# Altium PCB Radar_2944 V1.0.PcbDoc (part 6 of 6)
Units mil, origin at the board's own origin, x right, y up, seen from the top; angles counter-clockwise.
Board outline 3544.83 x 2556.65 mil, 8 copper layers (Top Layer, GND1, SIG1, PWR1, PWR2, SIG2, GND2, Bottom Layer), stack 55.2 mil thick; 301 components, 253 nets, 1055 pads, 1340 vias.
Unrouted connection lines stored in the file: 12.
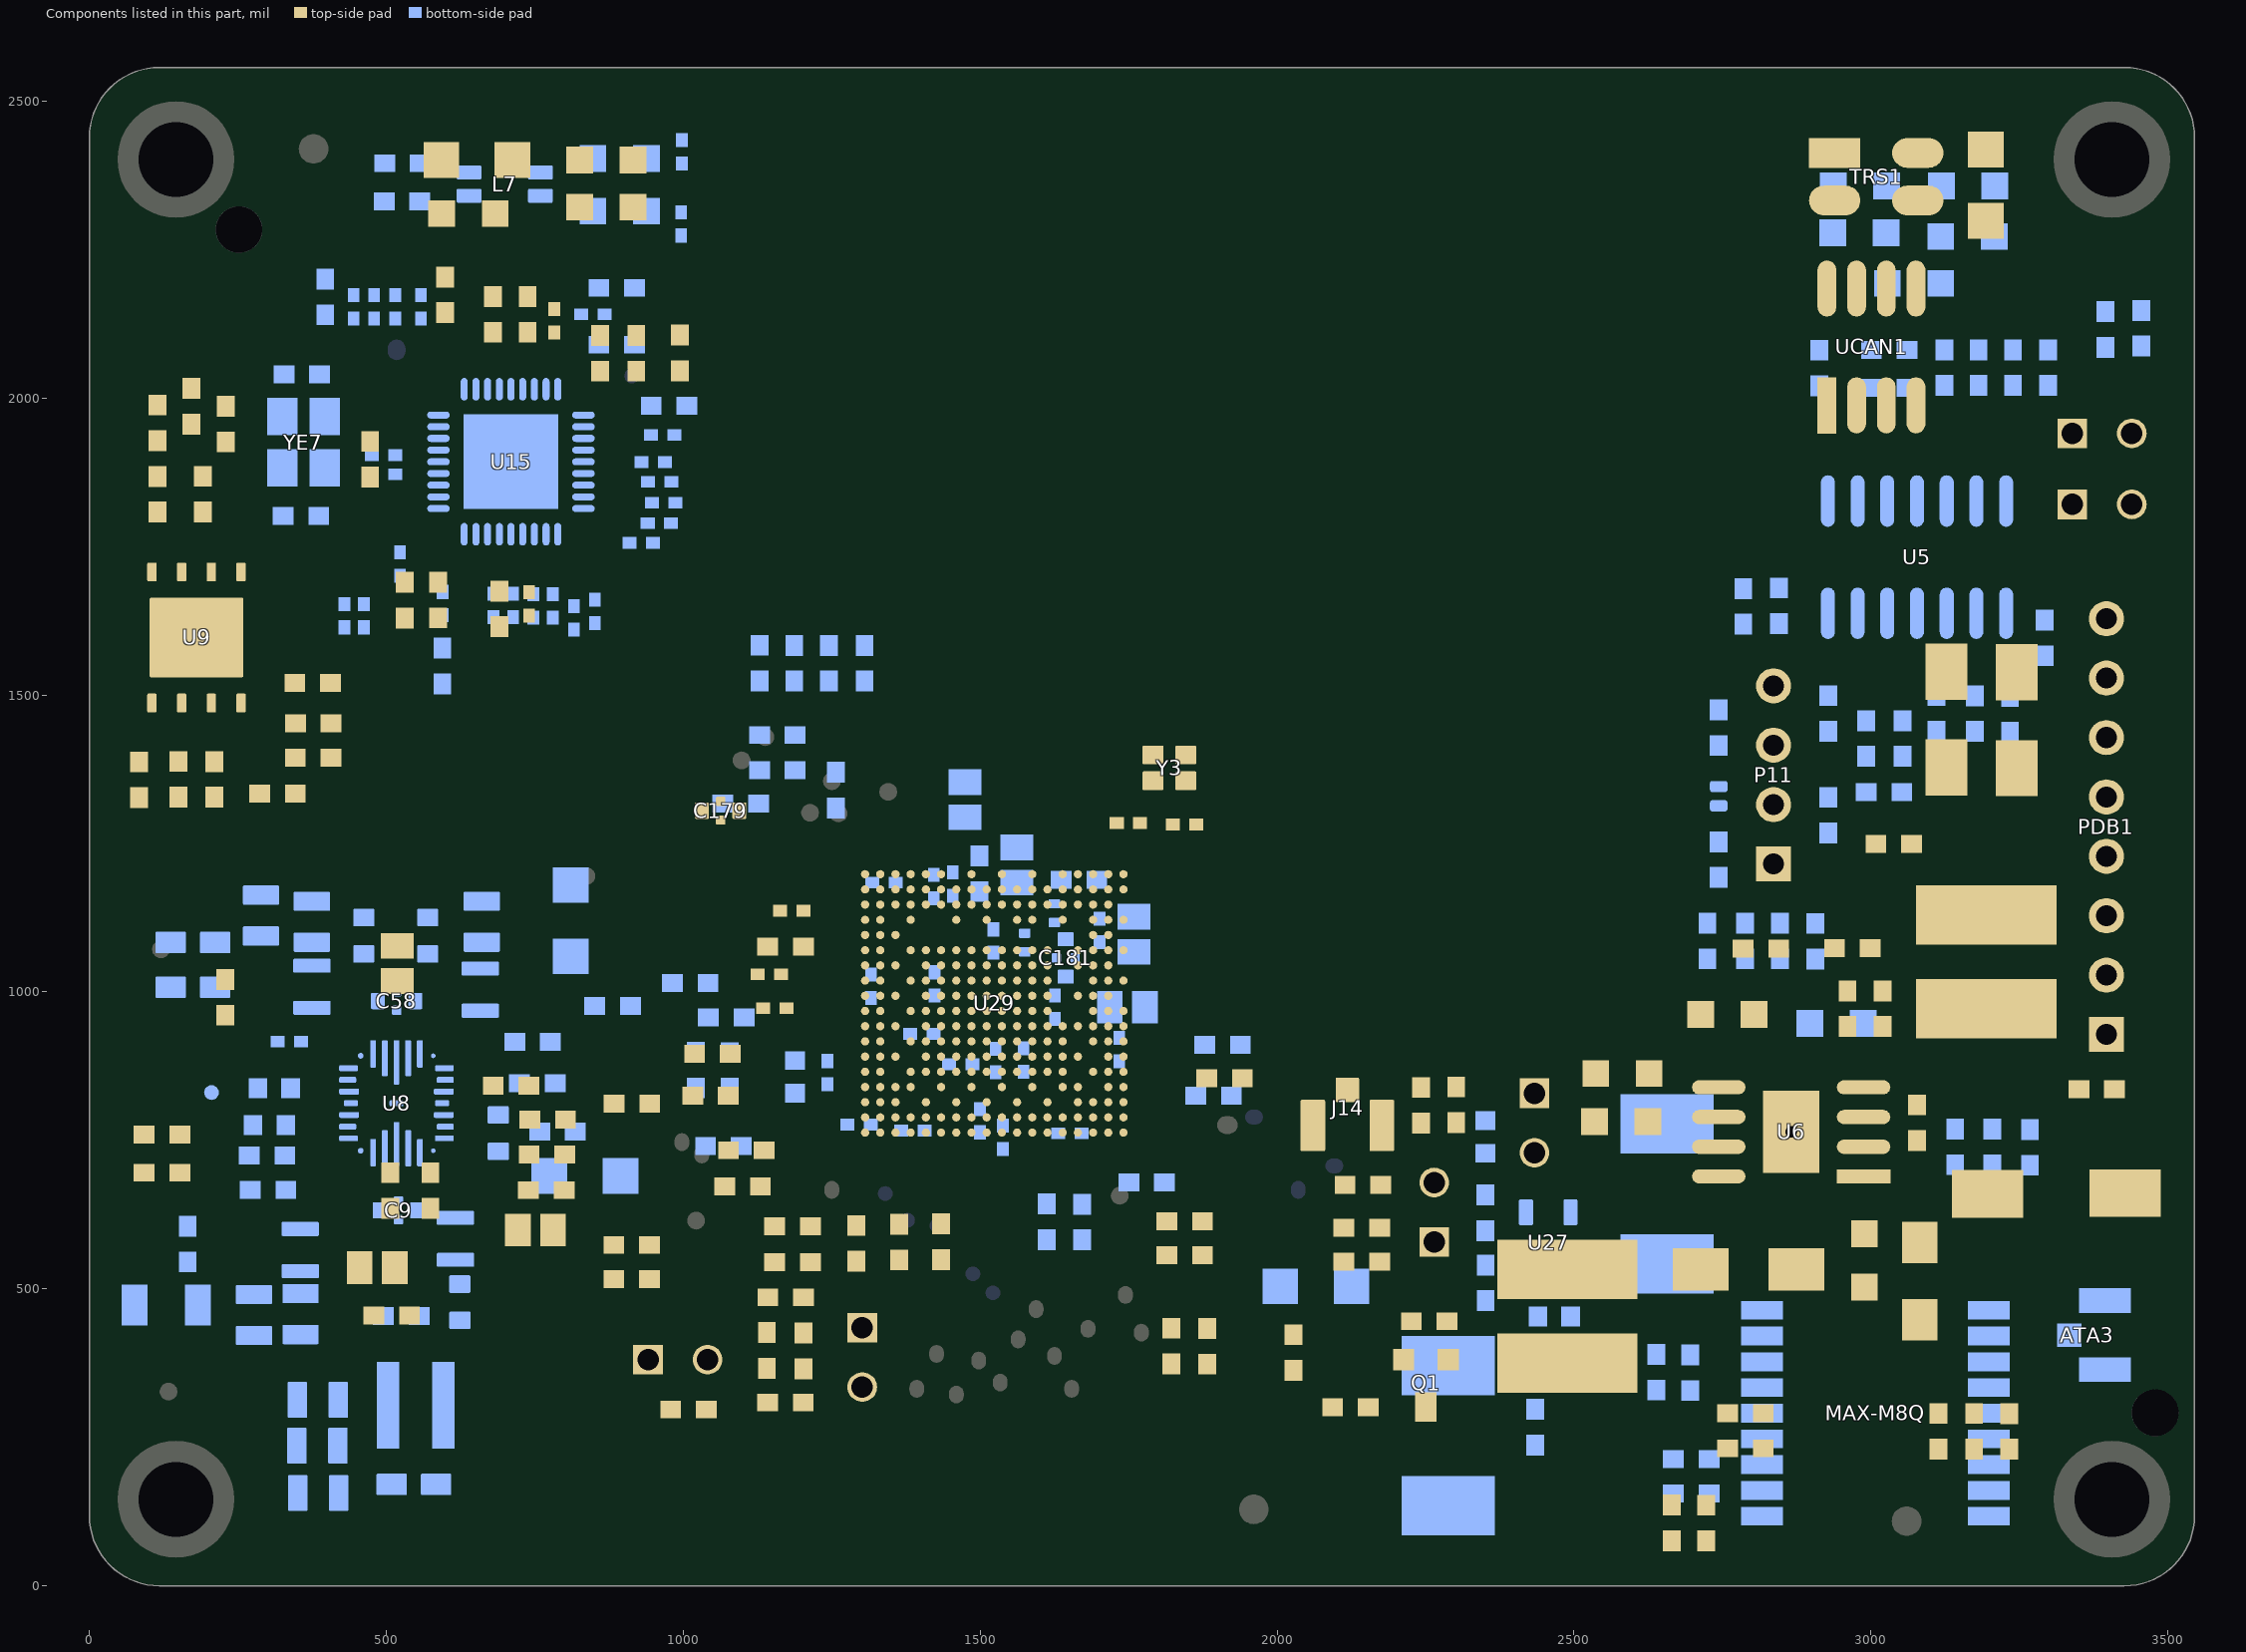
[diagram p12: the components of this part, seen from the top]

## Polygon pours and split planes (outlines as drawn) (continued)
no net on Bottom Solder "Bottom Solder-No Net" (solid, pour order 1578): 2638.93,2556.53 2638.93,1669.33 1203.32,1669.33 1203.32,2556.53
no net on Bottom Solder "Bottom Solder-No Net" (solid, pour order 1577): 1607.08,1043.38 1607.08,925.16 1441.11,925.16 1441.11,1043.38

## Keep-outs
GND1:
  circle w1: c1510.94,1172.58 r4.68
  circle w1: c1562.12,788.72 r6.17
  circle w1: c1562.25,763.01 r6.17
  circle w1: c1613.43,763.01 r6.17
  circle w1: c1613.31,788.72 r6.17
  circle w1: c1587.59,763.26 r6.17
  circle w1: c1587.71,788.72 r6.17
  circle w1: c1536.53,763.13 r6.17
  circle w1: c1536.53,788.72 r6.17
  circle w1: c1715.67,993.45 r4.68
  circle w1: c1715.67,1044.63 r4.68
  circle w1: c1715.67,1095.81 r4.68
  circle w1: c1715.67,1146.99 r4.68
  circle w1: c1613.31,1172.58 r4.68
  circle w1: c1562.12,1172.58 r4.68
  circle w1: c1459.76,1172.58 r4.68

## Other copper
Top Layer:
  pour cut-out: 549.41,2474.67 549.41,2261.15 1042.08,2261.15 1042.08,2474.67
  region net RX4: 1643.29,1585.2 1646.77,1585.2 1646.77,1632.45 1638.9,1632.45 1638.9,1676.74 1646.77,1676.74 1646.77,1723.98 1631.02,1723.98 1631.02,1767.45 1646.77,1767.45 1646.77,1814.69 1625.12,1814.69 1625.12,1857.68 1646.77,1857.68 1646.77,1904.93 1619.21,1904.93 1619.21,1947.53 1646.77,1947.53 1646.77,1994.77 1619.21,1994.77 1619.21,2037.37 1646.77,2037.37 1646.77,2084.61 1625.12,2084.61 1625.12,2127.61 1646.77,2127.61 1646.77,2174.85 1631.02,2174.85 1631.02,2218.43 1646.77,2218.43 1646.77,2265.68 1638.9,2265.68 1638.9,2309.85 1658.58,2309.85 1658.58,2265.68 1650.71,2265.68 1650.71,2218.43 1666.46,2218.43 1666.46,2174.85 1650.71,2174.85 1650.71,2127.61 1672.36,2127.61 1672.36,2084.61 1650.71,2084.61 1650.71,2037.37 1678.27,2037.37 1678.27,1994.77 1650.71,1994.77 1650.71,1947.53 1678.27,1947.53 1678.27,1904.93 1650.71,1904.93 1650.71,1857.68 1672.36,1857.68 1672.36,1814.69 1650.71,1814.69 1650.71,1767.45 1666.46,1767.45 1666.46,1723.98 1650.71,1723.98 1650.71,1676.74 1658.58,1676.74 1658.58,1632.45 1650.71,1632.45 1650.71,1585.2 1654.19,1585.2 1654.19,1564.93 1663.64,1564.93 1663.64,1554.02 1654.19,1554.02 1654.19,1530.09 1643.29,1530.09
  region net RX3: 1568.48,1585.2 1571.97,1585.2 1571.97,1632.45 1564.09,1632.45 1564.09,1676.74 1571.97,1676.74 1571.97,1723.98 1556.22,1723.98 1556.22,1767.45 1571.97,1767.45 1571.97,1814.69 1550.31,1814.69 1550.31,1857.68 1571.97,1857.68 1571.97,1904.93 1544.41,1904.93 1544.41,1947.53 1571.97,1947.53 1571.97,1994.77 1544.41,1994.77 1544.41,2037.37 1571.97,2037.37 1571.97,2084.61 1550.31,2084.61 1550.31,2127.61 1571.97,2127.61 1571.97,2174.85 1556.22,2174.85 1556.22,2218.43 1571.97,2218.43 1571.97,2265.68 1564.09,2265.68 1564.09,2309.85 1583.78,2309.85 1583.78,2265.68 1575.9,2265.68 1575.9,2218.43 1591.65,2218.43 1591.65,2174.85 1575.9,2174.85 1575.9,2127.61 1597.56,2127.61 1597.56,2084.61 1575.9,2084.61 1575.9,2037.37 1603.46,2037.37 1603.46,1994.77 1575.9,1994.77 1575.9,1947.53 1603.46,1947.53 1603.46,1904.93 1575.9,1904.93 1575.9,1857.68 1597.56,1857.68 1597.56,1814.69 1575.9,1814.69 1575.9,1767.45 1591.65,1767.45 1591.65,1723.98 1575.9,1723.98 1575.9,1676.74 1583.78,1676.74 1583.78,1632.45 1575.9,1632.45 1575.9,1585.2 1579.39,1585.2 1579.39,1564.93 1588.84,1564.93 1588.84,1554.02 1579.39,1554.02 1579.39,1530.09 1568.48,1530.09
  region net RX2: 1493.68,1585.2 1497.16,1585.2 1497.16,1632.45 1489.29,1632.45 1489.29,1676.74 1497.16,1676.74 1497.16,1723.98 1481.42,1723.98 1481.42,1767.45 1497.16,1767.45 1497.16,1814.69 1475.51,1814.69 1475.51,1857.68 1497.16,1857.68 1497.16,1904.93 1469.6,1904.93 1469.6,1947.53 1497.16,1947.53 1497.16,1994.77 1469.6,1994.77 1469.6,2037.37 1497.16,2037.37 1497.16,2084.61 1475.51,2084.61 1475.51,2127.61 1497.16,2127.61 1497.16,2174.85 1481.42,2174.85 1481.42,2218.43 1497.16,2218.43 1497.16,2265.68 1489.29,2265.68 1489.29,2309.85 1508.97,2309.85 1508.97,2265.68 1501.1,2265.68 1501.1,2218.43 1516.85,2218.43 1516.85,2174.85 1501.1,2174.85 1501.1,2127.61 1522.75,2127.61 1522.75,2084.61 1501.1,2084.61 1501.1,2037.37 1528.66,2037.37 1528.66,1994.77 1501.1,1994.77 1501.1,1947.53 1528.66,1947.53 1528.66,1904.93 1501.1,1904.93 1501.1,1857.68 1522.75,1857.68 1522.75,1814.69 1501.1,1814.69 1501.1,1767.45 1516.85,1767.45 1516.85,1723.98 1501.1,1723.98 1501.1,1676.74 1508.97,1676.74 1508.97,1632.45 1501.1,1632.45 1501.1,1585.2 1504.59,1585.2 1504.59,1564.93 1514.03,1564.93 1514.03,1554.02 1504.59,1554.02 1504.59,1530.09 1493.68,1530.09
  pour cut-out: 1854.8,1195.24 1755.86,1195.24 1749.93,1189.31 1749.93,1178.9 1753.68,1178.9 1760.1,1185.31 1858.97,1185.31 1921.25,1247.59 1921.25,1404.23 1841.33,1484.14 1717.48,1484.14 1688.56,1455.23 1688.56,1321.92 1678.5,1311.86 1678.5,1285.75 1672.48,1279.73 1672.48,1265.26 1644.34,1237.12 1644.34,1221.3 1654.33,1221.3 1654.33,1233.03 1682.52,1261.23 1682.53,1275.75 1688.56,1281.79 1688.56,1307.94 1698.56,1317.9 1698.57,1450.95 1721.75,1474.14 1837.29,1474.14 1911.22,1400.21 1911.22,1251.66
  region net TX4: 2527.29,1593.08 2530.77,1593.08 2530.77,1640.32 2522.9,1640.32 2522.9,1683.63 2530.77,1683.63 2530.77,1730.87 2515.02,1730.87 2515.02,1773.59 2530.77,1773.59 2530.77,1820.83 2509.12,1820.83 2509.12,1862.96 2530.77,1862.96 2530.77,1910.2 2503.21,1910.2 2503.21,1951.94 2530.77,1951.94 2530.77,1999.18 2503.21,1999.18 2503.21,2040.91 2530.77,2040.91 2530.77,2088.16 2509.12,2088.16 2509.12,2130.28 2530.77,2130.28 2530.77,2177.53 2515.02,2177.53 2515.02,2220.24 2530.77,2220.24 2530.77,2267.49 2522.9,2267.49 2522.9,2310.79 2542.58,2310.79 2542.58,2267.49 2534.71,2267.49 2534.71,2220.24 2550.46,2220.24 2550.46,2177.53 2534.71,2177.53 2534.71,2130.28 2556.36,2130.28 2556.36,2088.16 2534.71,2088.16 2534.71,2040.91 2562.27,2040.91 2562.27,1999.18 2534.71,1999.18 2534.71,1951.94 2562.27,1951.94 2562.27,1910.2 2534.71,1910.2 2534.71,1862.96 2556.36,1862.96 2556.36,1820.83 2534.71,1820.83 2534.71,1773.59 2550.46,1773.59 2550.46,1730.87 2534.71,1730.87 2534.71,1683.63 2542.58,1683.63 2542.58,1640.32 2534.71,1640.32 2534.71,1593.08 2538.19,1593.08 2538.19,1572.8 2547.64,1572.8 2547.64,1561.9 2538.19,1561.9 2538.19,1537.96 2527.29,1537.96
  region net TX2: 2064.45,1716.5 2067.94,1716.5 2067.94,1763.75 2060.06,1763.75 2060.06,1807.05 2067.94,1807.05 2067.94,1854.3 2052.19,1854.3 2052.19,1897.01 2067.94,1897.01 2067.94,1944.26 2046.28,1944.26 2046.28,1986.38 2067.94,1986.38 2067.94,2033.63 2040.38,2033.63 2040.38,2075.36 2067.94,2075.36 2067.94,2122.61 2040.38,2122.61 2040.38,2164.34 2067.94,2164.34 2067.94,2211.58 2046.28,2211.58 2046.28,2253.71 2067.94,2253.71 2067.94,2300.95 2052.19,2300.95 2052.19,2343.67 2067.94,2343.67 2067.94,2390.91 2060.06,2390.91 2060.06,2434.22 2079.75,2434.22 2079.75,2390.91 2071.87,2390.91 2071.87,2343.67 2087.62,2343.67 2087.62,2300.95 2071.87,2300.95 2071.87,2253.71 2093.53,2253.71 2093.53,2211.58 2071.87,2211.58 2071.87,2164.34 2099.43,2164.34 2099.43,2122.61 2071.87,2122.61 2071.87,2075.36 2099.43,2075.36 2099.43,2033.63 2071.87,2033.63 2071.87,1986.38 2093.53,1986.38 2093.53,1944.26 2071.87,1944.26 2071.87,1897.01 2087.62,1897.01 2087.62,1854.3 2071.87,1854.3 2071.87,1807.05 2079.75,1807.05 2079.75,1763.75 2071.87,1763.75 2071.87,1716.5 2075.36,1716.5 2075.36,1696.23 2084.81,1696.23 2084.81,1685.32 2075.36,1685.32 2075.36,1661.38 2064.45,1661.38
  region net TX3: 2218.74,1593.08 2222.23,1593.08 2222.23,1640.32 2214.35,1640.32 2214.35,1683.63 2222.23,1683.63 2222.23,1730.87 2206.48,1730.87 2206.48,1773.59 2222.23,1773.59 2222.23,1820.83 2200.57,1820.83 2200.57,1862.96 2222.23,1862.96 2222.23,1910.2 2194.67,1910.2 2194.67,1951.94 2222.23,1951.94 2222.23,1999.18 2194.67,1999.18 2194.67,2040.91 2222.23,2040.91 2222.23,2088.16 2200.57,2088.16 2200.57,2130.28 2222.23,2130.28 2222.23,2177.53 2206.48,2177.53 2206.48,2220.24 2222.23,2220.24 2222.23,2267.49 2214.35,2267.49 2214.35,2310.79 2234.04,2310.79 2234.04,2267.49 2226.16,2267.49 2226.16,2220.24 2241.91,2220.24 2241.91,2177.53 2226.16,2177.53 2226.16,2130.28 2247.82,2130.28 2247.82,2088.16 2226.16,2088.16 2226.16,2040.91 2253.72,2040.91 2253.72,1999.18 2226.16,1999.18 2226.16,1951.94 2253.72,1951.94 2253.72,1910.2 2226.16,1910.2 2226.16,1862.96 2247.82,1862.96 2247.82,1820.83 2226.16,1820.83 2226.16,1773.59 2241.91,1773.59 2241.91,1730.87 2226.16,1730.87 2226.16,1683.63 2234.04,1683.63 2234.04,1640.32 2226.16,1640.32 2226.16,1593.08 2229.65,1593.08 2229.65,1572.8 2239.1,1572.8 2239.1,1561.9 2229.65,1561.9 2229.65,1537.96 2218.74,1537.96
  region net TX1: 1910.2,1593.08 1913.68,1593.08 1913.68,1640.32 1905.81,1640.32 1905.81,1683.63 1913.68,1683.63 1913.68,1730.87 1897.94,1730.87 1897.94,1773.59 1913.68,1773.59 1913.68,1820.83 1892.03,1820.83 1892.03,1862.96 1913.68,1862.96 1913.68,1910.2 1886.13,1910.2 1886.13,1951.94 1913.68,1951.94 1913.68,1999.18 1886.13,1999.18 1886.13,2040.91 1913.68,2040.91 1913.68,2088.16 1892.03,2088.16 1892.03,2130.28 1913.68,2130.28 1913.68,2177.53 1897.94,2177.53 1897.94,2220.24 1913.68,2220.24 1913.68,2267.49 1905.81,2267.49 1905.81,2310.79 1925.5,2310.79 1925.5,2267.49 1917.62,2267.49 1917.62,2220.24 1933.37,2220.24 1933.37,2177.53 1917.62,2177.53 1917.62,2130.28 1939.28,2130.28 1939.28,2088.16 1917.62,2088.16 1917.62,2040.91 1945.18,2040.91 1945.18,1999.18 1917.62,1999.18 1917.62,1951.94 1945.18,1951.94 1945.18,1910.2 1917.62,1910.2 1917.62,1862.96 1939.28,1862.96 1939.28,1820.83 1917.62,1820.83 1917.62,1773.59 1933.37,1773.59 1933.37,1730.87 1917.62,1730.87 1917.62,1683.63 1925.5,1683.63 1925.5,1640.32 1917.62,1640.32 1917.62,1593.08 1921.11,1593.08 1921.11,1572.8 1930.55,1572.8 1930.55,1561.9 1921.11,1561.9 1921.11,1537.96 1910.2,1537.96
  region net RX1: 1418.88,1585.2 1422.36,1585.2 1422.36,1632.45 1414.49,1632.45 1414.49,1676.74 1422.36,1676.74 1422.36,1723.98 1406.61,1723.98 1406.61,1767.45 1422.36,1767.45 1422.36,1814.69 1400.71,1814.69 1400.71,1857.68 1422.36,1857.68 1422.36,1904.93 1394.8,1904.93 1394.8,1947.53 1422.36,1947.53 1422.36,1994.77 1394.8,1994.77 1394.8,2037.37 1422.36,2037.37 1422.36,2084.61 1400.71,2084.61 1400.71,2127.61 1422.36,2127.61 1422.36,2174.85 1406.61,2174.85 1406.61,2218.43 1422.36,2218.43 1422.36,2265.68 1414.49,2265.68 1414.49,2309.85 1434.17,2309.85 1434.17,2265.68 1426.3,2265.68 1426.3,2218.43 1442.05,2218.43 1442.05,2174.85 1426.3,2174.85 1426.3,2127.61 1447.95,2127.61 1447.95,2084.61 1426.3,2084.61 1426.3,2037.37 1453.86,2037.37 1453.86,1994.77 1426.3,1994.77 1426.3,1947.53 1453.86,1947.53 1453.86,1904.93 1426.3,1904.93 1426.3,1857.68 1447.95,1857.68 1447.95,1814.69 1426.3,1814.69 1426.3,1767.45 1442.05,1767.45 1442.05,1723.98 1426.3,1723.98 1426.3,1676.74 1434.17,1676.74 1434.17,1632.45 1426.3,1632.45 1426.3,1585.2 1429.78,1585.2 1429.78,1564.93 1439.23,1564.93 1439.23,1554.02 1429.78,1554.02 1429.78,1530.09 1418.88,1530.09
PWR1:
  rectangle net 3V3_VIO: 937.53,618.43 1020.12,715.13
  pour cut-out: 3325.13,506.91 3546.43,506.91 3546.43,343.74 3325.13,343.74
PWR2:
  pour cut-out: 3325.13,505.98 3546.43,505.98 3546.43,342.81 3325.13,342.82
GND1:
  pour cut-out: 3323.48,504.37 3544.79,504.37 3544.79,341.2 3323.48,341.2
  pour cut-out: 1760.1,1195.26 1755.88,1195.26 1749.93,1189.31 1749.93,1178.92 1753.7,1178.92 1760.1,1185.31 1858.97,1185.31 1921.25,1247.59 1921.25,1404.23 1841.33,1484.14 1717.48,1484.14 1688.56,1455.23 1688.56,1321.92 1678.5,1311.86 1678.5,1285.75 1672.48,1279.73 1672.48,1265.26 1644.34,1237.12 1644.34,1208.29 1654.33,1208.29 1654.33,1233.03 1682.52,1261.23 1682.53,1275.75 1688.56,1281.79 1688.56,1307.94 1698.56,1317.9 1698.57,1450.95 1721.75,1474.14 1837.29,1474.14 1911.22,1400.21 1911.22,1251.66 1854.8,1195.24
SIG1:
  pour cut-out: 3325.13,500.26 3546.43,500.26 3546.43,337.09 3325.13,337.09
SIG2:
  pour cut-out: 3325.13,502.89 3546.43,502.89 3546.43,339.72 3325.13,339.72
GND2:
  pour cut-out: 3323.48,503.85 3544.79,503.85 3544.79,340.68 3323.48,340.68
Bottom Layer:
  pour cut-out: 3323.48,459.27 3544.78,459.27 3544.78,387.91 3323.48,387.91
  pour cut-out: 281.83,934.75 281.83,970.05 307.75,995.97 326.76,976.97 326.76,934.75
  pour cut-out: 493.76,764.75 497.84,760.67 497.84,749.81 493.78,749.81
  pour cut-out: 537.44,759.66 539.88,762.11 541.79,762.11 541.79,748.66 540.33,747.2 537.4,750.13
  pour cut-out: 1150.05,2285.73 1065.93,2201.62 733.36,2201.62 733.36,1999.12 627.33,1999.12 627.33,2210.76 427.35,2210.76 376.47,2261.65 376.47,2435.6 451.12,2510.26 1048.09,2510.26 1115.83,2442.53 1150.05,2408.3 1150.05,2382.81
  pour cut-out: 1349.67,668.38 1349.67,692.07 1343.14,695.34 1335.7,691.05 1335.7,624.38 1342.88,617.19 1361.79,617.19 1368.82,624.22 1368.82,649.23
  pour cut-out: 1621.47,740.08 1652.97,708.59 1652.97,677.09 1621.47,677.09
  pour cut-out: 1328.45,918.68 1328.45,973.79 1332.75,973.79 1332.75,918.68

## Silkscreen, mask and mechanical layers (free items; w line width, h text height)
Top Overlay:
  rectangle: 2785.39,1556.02 2885.8,1591.85
  rectangle: 3444.43,1294.34 3478.01,1369.49
  lines w5: 2785.39,1164.33 2785.39,1557.54 2886.24,1557.54 cw(c2886.24,1557.35) 2886.37,1557.48 2886.37,1164.64 cw(c2885.93,1164.64) 2886.24,1164.33 2785.39,1164.33
  text "GND" at 342.44,2458.22 h30
  text "CAN唤醒" at 3289.05,2047.76 h60
  text "120欧" at 3138.7,1797.3 h60
  text "12V" at 3462.51,1621.92 h20
  text "ETH_P" at 3449.43,1518.91 h20
  text "ETH_N" at 3449.43,1420.78 h20
  text "GND" at 3483.01,1323.83 h20
  text "CAN1L" at 3451.36,1215.48 h20
  text "12V" at 2940.45,1151.43 h30
  text "1V8" at 771.62,1134.2 h30
  text "CAN1H" at 3451.36,1121.65 h20
  text "1V0" at 109.72,1120.36 h30
  text "CAN2L" at 3449.43,1017.96 h20
  text "CAN2H" at 3447.6,912.48 h20
  text "1.7V" at 2506.28,697.61 h30
  text "3V3IO" at 983.58,563.43 h30
  text "1V2" at 130.65,352.37 h30
  text "RST" at 854.12,277.92 h30
  text "3.3VIO" at 1771.82,270.49 h30
  text "SL_ST" at 1240.87,232.2 h40
  text "REG3.3V" at 1872.62,176.85 h30
  text "2944 V1.0" at 1320.37,143.04 h60
  text "Reg3.3V" at 2766.25,143.21 h30
  text "GND" at 3102.38,98.73 h30
  text "2024.07.29" at 1292.6,43.84 h60
Bottom Overlay:
  circle w6: c1871.1,537.18 r13.43
  region: 2785.55,1589.76 2785.55,1555.96 2887.31,1555.96 2887.31,1589.76
  rectangle: 3442.73,1293.89 3476.53,1372.1
  lines w5: 1615.15,1039.06 1615.15,1076.75 ; 1674.05,1044.4 1674.05,1069.58
  text "12V" at 3512.83,1623.21 h20
  text "ETH_P" at 3539.22,1518.41 h20
  text "ETH_N" at 3542.15,1420.18 h20
  text "GND" at 3535.12,1324.44 h20
  text "CAN1L" at 3535.12,1214.68 h20
  text "CAN1H" at 3540.12,1121.03 h20
  text "CAN2L" at 3540.12,1019.41 h20
  text "CAN2H" at 3540.12,912.72 h20
  text "2944 V1.0" at 1414.02,168.53 h60
  text "2024.07.29" at 1431.59,69.22 h60
M1 Board Outline:
  lines w2: 0.01,118.17 0.01,2438.42 ; 118.09,2556.53 3426.69,2556.53 ; 118.17,0.01 3426.49,0.01 ; 3544.78,117.99 3544.78,2438.42
  lines w2.01: -0.02,2438.42 cw(c118.09,2438.42) 118.09,2556.53 ; 0.06,118.17 ccw(c118.17,118.17) 118.17,0.06 ; 3426.49,-0.12 ccw(c3426.49,117.99) 3544.6,117.99 ; 3426.69,2556.53 cw(c3426.69,2438.42) 3544.8,2438.42
M6 Assembly Bottom:
  lines w4: 1701.83,1043.21 1701.83,1062.35
M10 Fab Notes:
  lines w1: 1364.04,1542.42 1401.46,1542.42 1401.46,1131.26 1418.89,1131.26 1690.08,1131.26 1690.08,1107.28 1690.08,955.74 2621.32,955.74 2621.32,2468.11 1364.04,2468.11 1364.04,1542.42 ; 1438.75,921.75 1614.13,921.75 1614.13,1044.62 1438.75,1044.62 1438.75,921.75
DXF_TX:
  drawing of 288 lines, arcs and shapes, not listed
DXF_RX:
  drawing of 498 lines, arcs and shapes, not listed

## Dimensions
3618.45,-2.24 to 3618.18,2557.04 on M2 Board Dimensions
3543.71,2570.71 to 0.2,2556.24 on M2 Board Dimensions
